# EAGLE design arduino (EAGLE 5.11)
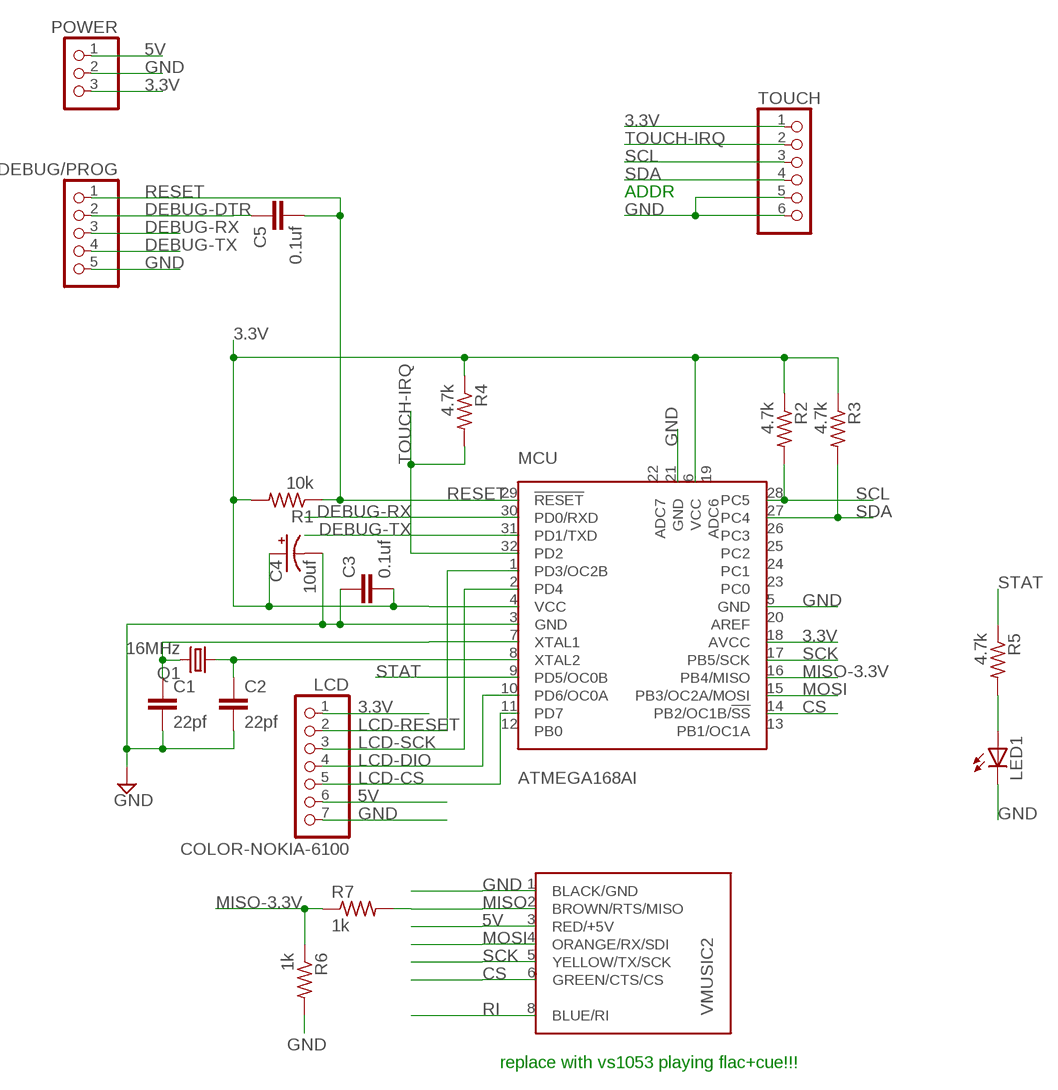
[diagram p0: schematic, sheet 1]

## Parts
C1  22pf  C-EUC0805  [C0805]
C2  22pf  C-EUC0805  [C0805]
C3  0.1uf  C-EUC0805  [C0805]
C4  10uf  CPOL-USE2-4  [E2-4]
C5  0.1uf  C-EUC0805  [C0805]
DEBUG/PROG  PINHD-1X5  [1X05]
LCD  COLOR-NOKIA-6100  PINHD-1X7  [1X07]
LED1  LED5MM  [LED5MM]
MCU  ATMEGA168AI  [TQFP32-08]
POWER  PINHD-1X3  [1X03]
Q1  16MHz  CRYSTALHC49U-V  [HC49U-V]
R1  10k  R-US_R0805  [R0805]
R2  4.7k  R-US_R1206  [R1206]
R3  4.7k  R-US_R1206  [R1206]
R4  4.7k  R-US_R1206  [R1206]
R5  4.7k  R-US_R1206  [R1206]
R6  1k  R-US_R1210  [R1210]
R7  1k  R-US_R1210  [R1210]
TOUCH  PINHD-1X6  [1X06]
VMUSIC2  VMUSIC2  [VMUSIC2]

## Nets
3.3V: C3.2 C4.+ LCD.1 MCU.4(VCC) MCU.6(VCC) MCU.18(AVCC) POWER.3 R1.2 R2.1 R3.1 R4.1 TOUCH.1
5V: LCD.6 POWER.1 VMUSIC2.3(RED/+5V)
CS: MCU.14(PB2/OC1B/!SS) VMUSIC2.6(GREEN/CTS/CS)
DEBUG-DTR: C5.1 DEBUG/PROG.2
DEBUG-RX: DEBUG/PROG.3 MCU.30(PD0/RXD)
DEBUG-TX: DEBUG/PROG.4 MCU.31(PD1/TXD)
GND: C1.2 C2.2 C3.1 C4.- DEBUG/PROG.5 LCD.7 LED1.K(C) MCU.3(GND) MCU.5(GND) MCU.21(GND) POWER.2 R6.2 TOUCH.5 TOUCH.6 VMUSIC2.1(BLACK/GND)
LCD-CS: LCD.5 MCU.11(PD7)
LCD-DIO: LCD.4 MCU.10(PD6/OC0A)
LCD-RESET: LCD.2 MCU.1(PD3/OC2B)
LCD-SCK: LCD.3 MCU.2(PD4)
MISO: R7.2 VMUSIC2.2(BROWN/RTS/MISO)
MISO-3.3V: MCU.16(PB4/MISO) R6.1 R7.1
MOSI: MCU.15(PB3/OC2A/MOSI) VMUSIC2.4(ORANGE/RX/SDI)
N$2: C2.1 MCU.8(XTAL2) Q1.1
N$3: C1.1 MCU.7(XTAL1) Q1.2
N$4: LED1.A R5.2
RESET: C5.2 DEBUG/PROG.1 MCU.29(!RESET) R1.1
RI: VMUSIC2.8(BLUE/RI)
SCK: MCU.17(PB5/SCK) VMUSIC2.5(YELLOW/TX/SCK)
SCL: MCU.28(PC5) R2.2 TOUCH.3
SDA: MCU.27(PC4) R3.2 TOUCH.4
STAT: MCU.9(PD5/OC0B) R5.1
TOUCH-IRQ: MCU.32(PD2) R4.2 TOUCH.2
Unconnected: MCU.12(PB0) MCU.13(PB1/OC1A) MCU.19(ADC6) MCU.20(AREF) MCU.22(ADC7) MCU.23(PC0) MCU.24(PC1) MCU.25(PC2) MCU.26(PC3)

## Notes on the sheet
- ADDR
- replace with vs1053 playing flac+cue!!!

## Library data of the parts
C1-C3 C5 = rcl:C-EU: CAPACITOR, European symbol
C4 = rcl:CPOL-US: POLARIZED CAPACITOR, American symbol
DEBUG/PROG = pinhead:PINHD-1X5: PIN HEADER
LCD = pinhead:PINHD-1X7: PIN HEADER
LED1 = led:LED: LED
MCU = trl:ATMEGA168
POWER = pinhead:PINHD-1X3: PIN HEADER
Q1 = crystal:CRYSTAL: CRYSTAL; OC_FARNELL: 1666969; OC_NEWARK: unknown
R1-R7 = resistor:R-US_: RESISTOR, American symbol
TOUCH = pinhead:PINHD-1X6: PIN HEADER
VMUSIC2 = trl:VMUSIC2

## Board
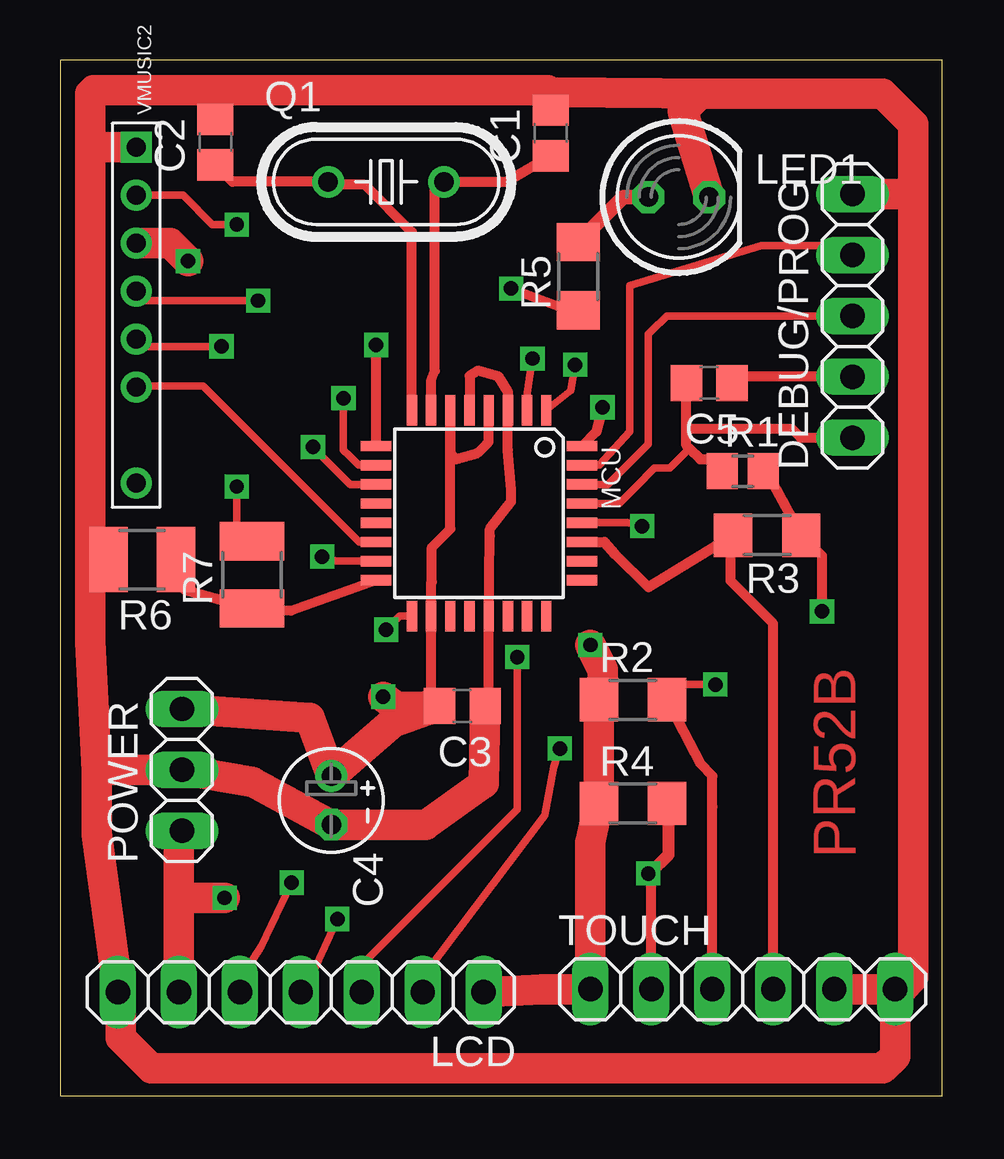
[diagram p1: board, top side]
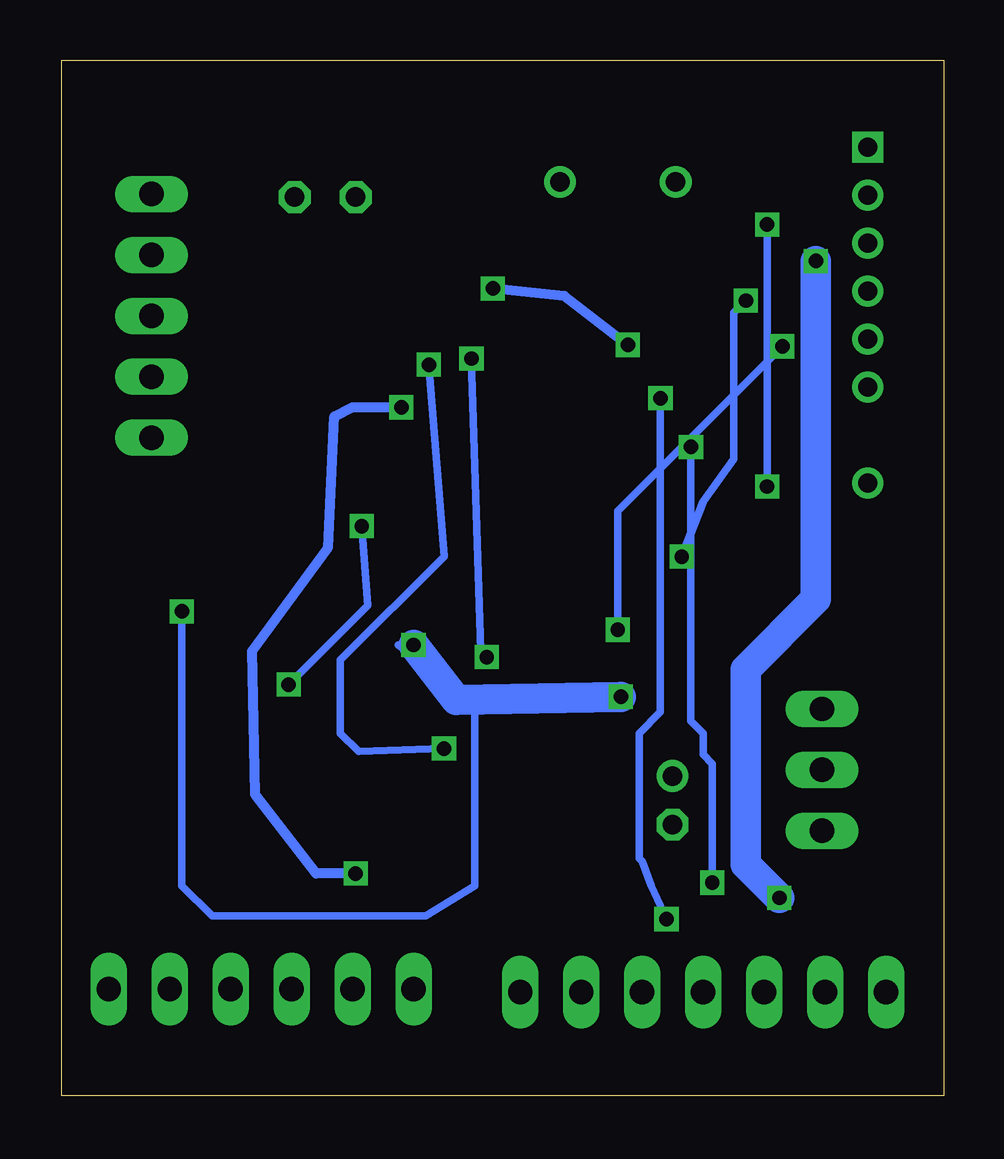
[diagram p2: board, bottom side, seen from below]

Size 36.75 x 43.17 mm. Coordinates in mm from the lower left corner, seen from the top.
Outline: 0,0 36.75,0 36.75,43.17 0,43.17 0,0
Copper layers (1*16): Top 0.035mm / dielectric 1.5mm / Bottom 0.035mm
Design rules "default": minimum track width 10mil, minimum drill 24mil, track to track 8mil, track to pad 8mil, pad to pad 8mil, via to via 8mil, smd to smd 8mil, copper to edge 40mil, drill to drill 8mil, minimum pad ring 10mil, minimum via ring 8mil, stop-mask expansion 4mil, vias tented up to drill 0mil, thermal gap 10mil

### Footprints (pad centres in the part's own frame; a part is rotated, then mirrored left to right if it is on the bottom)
C0805 = smd 1.3 x 1.5: 1 -0.95,0; 2 0.95,0
E2-4 = drill 0.813 pad 1.27 round: + -1.016,0 | drill 0.813 pad 1.27 octagon: - 1.016,0
1X05 = drill 1.016 long: 1 -5.08,0; 2 -2.54,0; 3 0,0; 4 2.54,0; 5 5.08,0
1X07 = drill 1.016 long: 1 -7.62,0; 2 -5.08,0; 3 -2.54,0; 4 0,0; 5 2.54,0; 6 5.08,0; 7 7.62,0
LED5MM = drill 0.813 octagon: A -1.27,0; K 1.27,0
TQFP32-08 = smd 1.27 x 0.432: 1 -3.563,2.61; 2 -3.563,1.81; 3 -3.563,1.01; 4 -3.563,0.21; 5 -3.563,-0.59; 6 -3.563,-1.39; 7 -3.563,-2.19; 8 -3.563,-2.99; 17 5.023,-2.99; 18 5.023,-2.19; 19 5.023,-1.39; 20 5.023,-0.59; 21 5.023,0.21; 22 5.023,1.01; 23 5.023,1.81; 24 5.023,2.61 | smd 0.432 x 1.27: 9 -2.07,-4.483; 10 -1.27,-4.483; 11 -0.47,-4.483; 12 0.33,-4.483; 13 1.13,-4.483; 14 1.93,-4.483; 15 2.73,-4.483; 16 3.53,-4.483; 25 3.53,4.103; 26 2.73,4.103; 27 1.93,4.103; 28 1.13,4.103; 29 0.33,4.103; 30 -0.47,4.103; 31 -1.27,4.103; 32 -2.07,4.103
1X03 = drill 1.016 long: 1 -2.54,0; 2 0,0; 3 2.54,0
HC49U-V = drill 0.813 round: 1 -2.413,0; 2 2.413,0
R0805 = smd 1.3 x 1.5: 1 -0.85,0; 2 0.85,0
R1206 = smd 1.6 x 1.803: 1 -1.422,0; 2 1.422,0
R1210 = smd 1.6 x 2.7: 1 -1.4,0; 2 1.4,0
1X06 = drill 1.016 long: 1 -6.35,0; 2 -3.81,0; 3 -1.27,0; 4 1.27,0; 5 3.81,0; 6 6.35,0
VMUSIC2 = drill 0.8 square: 1 5,0 | drill 0.8 round: 2 3,0; 3 1,0; 4 -1,0; 5 -3,0; 6 -5,0; 8 -9,0

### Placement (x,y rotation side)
C1  20.45,40.13 90 top
C2  6.48,39.75 90 top
C3  16.76,16.26 180 top
C4  11.3,12.32 270 top
C5  27.05,29.72 180 top
DEBUG/PROG  33.02,32.51 90 top
LCD  10.03,4.32 180 top
LED1  25.78,37.46 0 top
MCU  17.65,25.02 270 top
POWER  5.08,13.59 90 top
Q1  13.59,38.1 0 top
R1  28.45,26.04 0 top
R2  23.88,16.51 0 top
R3  29.46,23.37 180 top
R4  23.88,12.19 0 top
R5  21.59,34.16 90 top
R6  3.43,22.35 180 top
R7  8,21.72 90 top
TOUCH  28.45,4.45 0 top
VMUSIC2  3.17,34.54 90 top

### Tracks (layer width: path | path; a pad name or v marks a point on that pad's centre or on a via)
3.3V  (via drill 0.6)
  Top 0.406: 15.35,16.09 15.46,16.21 MCU.18 15.46,21.39 15.49,21.42 15.49,22.86 16.26,23.63 MCU.6 16.26,26.79 16.51,26.54 17.4,26.8 | 17.4,26.8 17.78,27.18 | R1.2 29.62,25.72 R3.1 31.75,22.5 v31.75,20.19 | MCU.4 17.86,27.26 17.4,26.8
  Top 1.27: POWER.3 10.41,15.75 C4.+ 13.84,15.55 C3.2 15.29,16.26 15.24,16.21 | LCD.1 20.07,4.45 TOUCH.1 22.1,10.57 R4.1 R2.1 22.48,16.87 22.61,17.4 22.61,17.78 v22.1,18.8 | 15.24,16.21 14.02,16.21 v13.46,16.64 | 15.24,16.21 15.46,16.21 15.35,16.09
  Bottom 0.305: v22.1,18.8 22.73,18.8 19.56,16.38 19.56,8.76 21.59,7.49 30.48,7.49 31.75,8.76 v31.75,20.19
  Bottom 1.27: v13.46,16.64 20.32,16.51 v22.1,18.8
5V  (via drill 0.6)
  Top 1.27: LCD.6 4.95,8.51 | 4.95,8.51 4.95,10.92 POWER.1 | VMUSIC2.3 4.59,35.54 v5.33,34.8 | v6.86,8.25 5.21,8.25 4.95,8.51
  Bottom 1.27: v5.33,34.8 5.33,20.7 8.26,17.78 8.26,9.65 v6.86,8.25
CS
  Top 0.305: MCU.14 12.47,23.09 12.32,23.24 5.97,29.59 3.22,29.59 VMUSIC2.6
DEBUG-DTR
  Top 0.406: DEBUG/PROG.2 28.25,29.97 C5.1
DEBUG-RX
  Top 0.305: MCU.30 22.82,25.49 23.88,26.54 24.51,27.18 24.51,31.75 24.64,31.88 25.27,32.51 DEBUG/PROG.3
DEBUG-TX
  Top 0.305: MCU.31 22.48,26.29 23.75,27.69 23.75,33.78 29.21,35.43 32.64,35.43 DEBUG/PROG.4
GND
  Top 0.406: MCU.5 17.06,30.02 17.4,30.23 18.29,29.97 18.67,29.34 18.67,28.7 MCU.3 18.66,26.93 18.8,25.27 18.8,24.77 17.91,23.62 17.91,23.34 MCU.21 17.86,16.41 C3.1
  Top 1.27: 6.35,41.91 1.4,41.91 1.27,41.78 1.27,39.24 | 1.27,39.24 1.27,25.27 1.27,22.73 | 1.27,22.73 1.27,21.84 R6.2 | C3.1 17.65,13.01 15.24,11.3 13.97,11.3 C4.- 8,13.08 POWER.2 1.91,13.59 1.52,13.21 1.52,10.92 | C2.2 6.48,41.78 6.35,41.91 | 20.38,41.85 27.43,41.78 | LED1.K 25.94,41.05 26.67,41.78 27.43,41.78 | 2.54,3.56 2.54,4.19 LCD.7 | 2.54,3.56 2.54,2.41 3.81,1.14 34.29,1.14 34.8,1.65 TOUCH.6 | 27.43,41.78 34.29,41.78 35.56,40.51 35.56,37.97 | 35.56,37.97 35.56,6.22 35.56,5.21 | 6.35,41.91 20.32,41.91 20.38,41.85 | C1.2 20.45,41.78 20.38,41.85 | 2.54,3.56 1.52,10.92 | 1.27,22.73 1.27,18.92 1.52,13.59 1.52,10.92 | DEBUG/PROG.5 35.18,37.59 35.56,37.97 | VMUSIC2.1 1.57,39.54 1.27,39.24 | TOUCH.6 35.05,4.45 35.56,4.95 | TOUCH.5 TOUCH.6
LCD-CS  (via drill 0.6)
  Top 0.305: MCU.11 12.1,25.49 v10.54,27.05 | LCD.5 7.49,4.83 8.38,6.22 v9.65,8.89
  Bottom 0.305: v10.54,27.05 10.54,15.62 10.03,15.11 10.03,14.22 9.65,13.84 9.65,9.27 | 9.65,9.27 9.4,9.14 9.65,9.27 | v9.65,8.89 9.65,9.27
LCD-DIO  (via drill 0.6)
  Top 0.305: MCU.10 12.45,26.29 12.06,26.67 11.81,26.92 v11.81,29.08 | v11.56,7.37 10.29,4.57 LCD.4
  Bottom 0.305: v11.81,29.08 11.81,16 12.7,15.11 12.7,9.91 12.57,9.78 12.19,8.76 v11.56,7.37
LCD-RESET  (via drill 0.6)
  Top 0.305: MCU.1 21.28,29.41 v21.46,30.48 | v20.83,14.48 20.7,14.1 20.57,13.72 20.19,11.68 15.11,4.95 LCD.2
  Bottom 0.305: v21.46,30.48 20.83,22.48 25.15,18.16 25.15,15.11 24.38,14.35 v20.83,14.48
LCD-SCK  (via drill 0.6)
  Top 0.305: LCD.3 12.57,5.46 14.86,7.75 18.92,11.81 19.05,11.94 19.05,12.57 v19.05,18.29 | MCU.2 19.46,29.3 v19.68,30.73
  Bottom 0.305: v19.68,30.73 19.3,18.54 v19.05,18.29
MISO  (via drill 0.6)
  Top 0.305: VMUSIC2.2 5.13,37.54 6.35,36.32 v7.37,36.32 | v7.37,25.4 7.37,23.75 R7.2
  Bottom 0.305: v7.37,36.32 v7.37,25.4
MISO-3.3V
  Top 0.406: R6.1 5.21,21.08 R7.1 9.62,20.22 MCU.16
MOSI  (via drill 0.6)
  Top 0.305: MCU.15 11.49,22.29 v10.92,22.48 | v8.26,33.15 3.57,33.15 VMUSIC2.4
  Bottom 0.305: v10.92,22.48 10.03,24.77 8.76,26.54 8.76,32.64 v8.26,33.15
N$2
  Top 0.406: MCU.8 14.66,36.01 12.7,37.97 11.3,37.97 Q1.1 7.18,38.1 C2.1
N$3
  Top 0.406: MCU.7 15.46,29.81 15.62,30.23 15.62,37.97 Q1.2 18.6,38.1 C1.1
N$4
  Top 0.61: LED1.A 23.47,37.46 R5.2
RESET
  Top 0.305: MCU.29 23.29,24.69 24,25.4 24.77,26.16 25.4,26.16 26.23,26.99
  Top 0.406: 26.1,27.81 26.1,27.11 26.23,26.99 26.67,26.54 27.09,26.54 R1.1 | 26.1,27.81 C5.2 | DEBUG/PROG.1 30.86,27.43 30.48,27.81 26.1,27.81
SCK  (via drill 0.6)
  Top 0.305: MCU.17 14.15,20 v13.59,19.43 | v6.73,31.24 3.48,31.24 VMUSIC2.5
  Bottom 0.305: v13.59,19.43 13.59,24.38 v6.73,31.24
SCL  (via drill 0.6)
  Top 0.305: MCU.28 23.64,23.89 v24.26,23.75 | v27.3,17.14 25.93,17.14 R2.2
  Top 0.406: TOUCH.3 27.18,12.06 27.18,13.33 26.7,13.84 R2.2
  Bottom 0.305: v24.26,23.75 24,20.45 v27.3,17.14
SDA
  Top 0.406: MCU.27 22.68,23.09 23.11,22.58 24.51,21.21 R3.2 27.94,23.27 27.94,21.46 29.72,19.69 TOUCH.4
STAT  (via drill 0.6)
  Top 0.406: MCU.9 v13.17,31.3 | v18.8,33.65 21.49,32.64 R5.1
  Bottom 0.406: v13.17,31.3 15.81,33.34 v18.8,33.65
TOUCH-IRQ  (via drill 0.6)
  Top 0.406: TOUCH.2 24.64,9.27 25.4,10.03 25.4,12.09 R4.2 25.3,10.06 v24.51,9.27 | v22.61,28.7 22.35,27.69 MCU.32
  Bottom 0.406: v24.51,9.27 26.16,9.27 28.7,12.57 28.83,18.54 25.65,22.86 25.4,28.32 24.64,28.7 v22.61,28.7

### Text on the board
Top: PR52B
